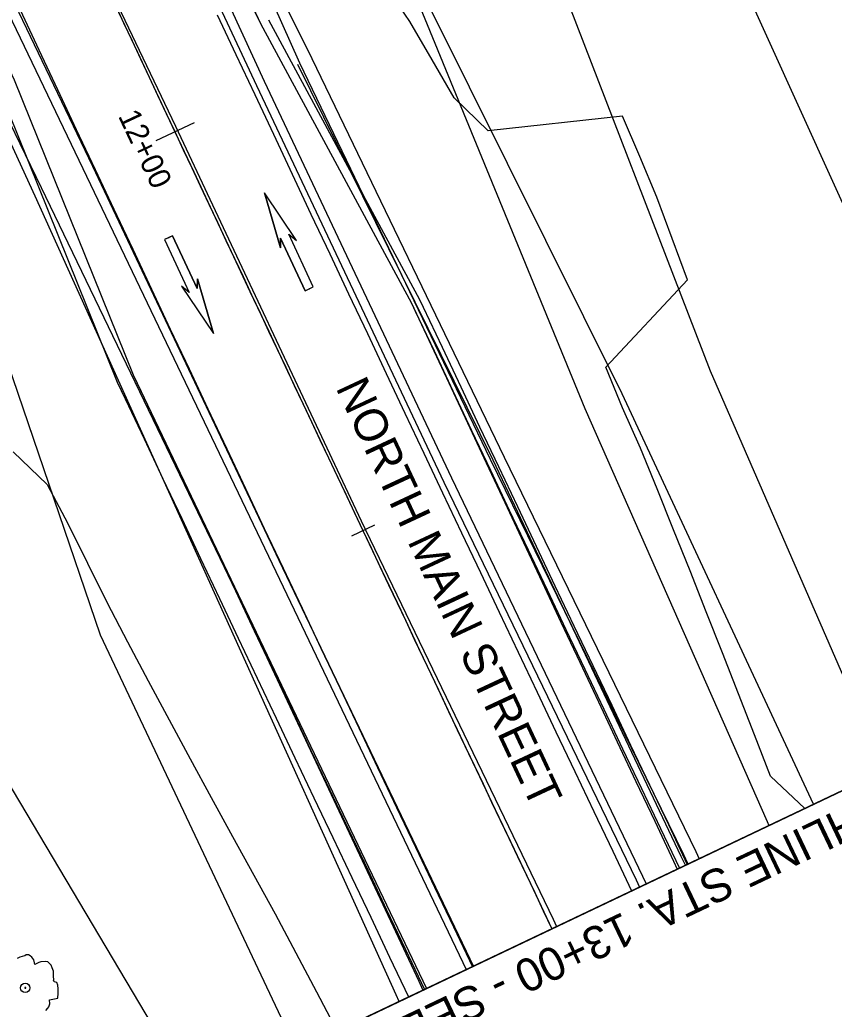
# Model space of a CAD drawing. Extents: x 1040567 to 1041254, y 1126791 to 1127594.
# Drawn here: x 1041010.6 to 1041103, y 1126935.4 to 1127047.7 of the extents above; entities that cross this region are included whole.
import ezdxf

# ---------------------------------------------------------------- set-up
doc = ezdxf.new("R2010")
doc.units = 0
for name, color, linetype in [('AC_P', 7, 'Continuous'), ('ACSR_P_T', 7, 'Continuous'), ('ACSRT_P', 7, 'Continuous'), ('clip boundary', 7, 'Continuous'), ('LABL', 7, 'Continuous'), ('LELB', 7, 'Continuous'), ('LFILL_P', 7, 'Continuous'), ('LTD', 7, 'Continuous'), ('NML_P', 7, 'Continuous'), ('NML_P_T', 7, 'Continuous'), ('O_Details_Text Title and Subtitle Proposed_P_T', 7, 'Continuous'), ('PE', 7, 'Continuous'), ('PE_P', 7, 'Continuous'), ('PET_P', 7, 'Continuous'), ('PSU', 7, 'Continuous'), ('RBS_P', 7, 'Continuous'), ('RGB_P', 7, 'Continuous'), ('RGC', 7, 'Continuous'), ('STFBY', 7, 'Continuous'), ('STFBY_P', 7, 'Continuous'), ('STSEW', 7, 'Continuous'), ('STSEY_P_T', 7, 'Continuous'), ('UEO', 7, 'Continuous')]:
    doc.layers.add(name, color=color, linetype=linetype)

msp = doc.modelspace()

# ---------------------------------------------------------------- linework, layer by layer
at = {"layer": 'AC_P'}
msp.add_arc((1059129.31, 1135540.78), 20000, 205.038741, 205.455638, dxfattribs=at)
at = {"layer": 'ACSRT_P'}
for points in [[(1041030.36, 1127035.96), (1041026.02, 1127033.92)], [(1041050.81, 1126990.33), (1041048.21, 1126989.09)], [(1041073.11, 1126945.57), (1041068.78, 1126943.51)]]:
    msp.add_lwpolyline(points, dxfattribs=at)
at = {"layer": 'clip boundary'}
msp.add_lwpolyline([(1040984.84, 1127512.73), (1041214.88, 1127013.05), (1040933.62, 1126879.17), (1040829.04, 1127018.95), (1040710.75, 1127268.88), (1040738.34, 1127281.77), (1040695.57, 1127374.92)], close=True, dxfattribs=at)
at = {"layer": 'LABL'}
msp.add_lwpolyline([(1041100.61, 1126958.66), (1041100.32, 1126959.26), (1041078.9, 1127005.21), (1041057.26, 1127048.74), (1041046.69, 1127067.39), (1041035.09, 1127091.47)], dxfattribs=at)
at = {"layer": 'LELB'}
for points in [[(1041108.64, 1126962.48), (1041088.94, 1127007.81), (1041071.29, 1127053.6), (1041055, 1127089.77)], [(1041025.59, 1127087.09), (1041045.55, 1127067.24), (1041055.92, 1127049.25), (1041074.68, 1127003.57), (1041095.34, 1126956.71), (1041095.55, 1126956.25)], [(1040987.11, 1127074.81), (1040992.41, 1127065.56), (1040989.3, 1127059.25), (1040989.75, 1127046.81), (1041003.6, 1127024.16), (1041003.93, 1127024.17), (1041019.73, 1126977.88), (1041041.18, 1126932.42), (1041041.98, 1126930.75)], [(1041030.52, 1126925.29), (1041030.18, 1126925.98), (1041006.02, 1126966.59), (1040984.12, 1127013.45), (1040964.74, 1127050.78), (1040957.76, 1127065.57)]]:
    msp.add_lwpolyline(points, dxfattribs=at)
at = {"layer": 'LFILL_P'}
for points in [[(1041099.63, 1126958.19), (1041095.72, 1126961.86), (1041093.92, 1126966.53), (1041092.11, 1126971.2), (1041090.28, 1126975.86), (1041088.44, 1126980.51), (1041086.6, 1126985.16), (1041084.73, 1126989.8), (1041082.86, 1126994.44), (1041080.98, 1126999.07), (1041078.96, 1127003.64), (1041077.05, 1127008.26), (1041086.3, 1127018.15), (1041084.57, 1127022.85), (1041082.84, 1127027.55), (1041080.92, 1127032.16), (1041078.95, 1127036.74), (1041063.72, 1127035.08), (1041059.87, 1127038.79), (1041057.37, 1127043.13), (1041054.82, 1127047.45), (1041052.01, 1127051.65)], [(1041009.84, 1126998.65), (1041013.69, 1126994.93), (1041016.04, 1126990.5), (1041018.26, 1126986.01), (1041020.51, 1126981.53), (1041022.8, 1126977.08), (1041025.16, 1126972.65), (1041027.53, 1126968.24), (1041029.91, 1126963.82), (1041032.31, 1126959.42), (1041034.72, 1126955.02), (1041037.15, 1126950.63), (1041039.54, 1126946.22), (1041041.89, 1126941.8), (1041044.24, 1126937.37), (1041046.58, 1126932.94)]]:
    msp.add_lwpolyline(points, dxfattribs=at)
at = {"layer": 'LTD'}
for points in [[(1041014.8, 1126938.43), (1041014.53, 1126938.53), (1041014.44, 1126938.65), (1041014.47, 1126938.74), (1041014.41, 1126939.17), (1041014.41, 1126939.72), (1041014.29, 1126940.12), (1041014.14, 1126940.42), (1041013.78, 1126940.78), (1041013.51, 1126940.84), (1041012.98, 1126940.78), (1041012.76, 1126940.72), (1041012.37, 1126940.51), (1041012.31, 1126940.48), (1041012.25, 1126940.69), (1041012.19, 1126941.02), (1041011.98, 1126941.33), (1041011.77, 1126941.48), (1041011.59, 1126941.57), (1041011.34, 1126941.57), (1041011.16, 1126941.48), (1041010.86, 1126941.39), (1041010.62, 1126941.33), (1041010.32, 1126941.15)], [(1041011.27, 1126937.83), (1041011.27, 1126937.83), (1041011.27, 1126937.83), (1041011.27, 1126937.85), (1041011.27, 1126937.85), (1041011.27, 1126937.85), (1041011.27, 1126937.86), (1041011.25, 1126937.86), (1041011.25, 1126937.86), (1041011.25, 1126937.86), (1041011.25, 1126937.86), (1041011.25, 1126937.88), (1041011.24, 1126937.88), (1041011.24, 1126937.88), (1041011.24, 1126937.88), (1041011.22, 1126937.88), (1041011.22, 1126937.88), (1041011.22, 1126937.88), (1041011.21, 1126937.88), (1041011.21, 1126937.88), (1041011.21, 1126937.88), (1041011.19, 1126937.88), (1041011.19, 1126937.86), (1041011.19, 1126937.86), (1041011.19, 1126937.86), (1041011.18, 1126937.86), (1041011.18, 1126937.86), (1041011.18, 1126937.85), (1041011.18, 1126937.85), (1041011.18, 1126937.85), (1041011.18, 1126937.83), (1041011.18, 1126937.83), (1041011.18, 1126937.83), (1041011.18, 1126937.82), (1041011.18, 1126937.82), (1041011.18, 1126937.82), (1041011.18, 1126937.8), (1041011.18, 1126937.8), (1041011.19, 1126937.8), (1041011.19, 1126937.8), (1041011.19, 1126937.79), (1041011.19, 1126937.79), (1041011.21, 1126937.79), (1041011.21, 1126937.79), (1041011.21, 1126937.79), (1041011.22, 1126937.79), (1041011.22, 1126937.79), (1041011.22, 1126937.79), (1041011.24, 1126937.79), (1041011.24, 1126937.79), (1041011.24, 1126937.79), (1041011.25, 1126937.79), (1041011.25, 1126937.79), (1041011.25, 1126937.8), (1041011.25, 1126937.8), (1041011.25, 1126937.8), (1041011.27, 1126937.8), (1041011.27, 1126937.82), (1041011.27, 1126937.82), (1041011.27, 1126937.82), (1041011.27, 1126937.83)], [(1041014.92, 1126936.66), (1041014.96, 1126937.23), (1041014.96, 1126937.71), (1041014.9, 1126938.14), (1041014.8, 1126938.43)], [(1041013.55, 1126935.25), (1041013.78, 1126935.52), (1041013.9, 1126935.7), (1041013.99, 1126936.04), (1041013.96, 1126936.47), (1041014.17, 1126936.5), (1041014.92, 1126936.66)]]:
    msp.add_lwpolyline(points, dxfattribs=at)
msp.add_circle((1041011.22, 1126937.83), 0.533, dxfattribs=at)
at = {"layer": 'NML_P'}
msp.add_line((1040940.57, 1126882.48), (1041214.88, 1127013.05), dxfattribs=at)
at = {"layer": 'O_Details_Text Title and Subtitle Proposed_P_T'}
for p, q in [((1041040.15, 1127021.79), (1041038.35, 1127028.01)), ((1041041.96, 1127022.63), (1041038.35, 1127028.01)), ((1041041.09, 1127023.33), (1041041.96, 1127022.63)), ((1041027.48, 1127022.93), (1041027.45, 1127022.92)), ((1041027.48, 1127022.91), (1041027.46, 1127022.9)), ((1041030.75, 1127018.28), (1041032.55, 1127012.06)), ((1041028.94, 1127017.43), (1041032.55, 1127012.06)), ((1041029.82, 1127016.74), (1041028.94, 1127017.43)), ((1041043.42, 1127017.15), (1041043.44, 1127017.17)), ((1041043.43, 1127017.14), (1041043.45, 1127017.15))]:
    msp.add_line(p, q, dxfattribs=at)
at = {"layer": 'PE'}
for points in [[(1041025.42, 1127071.09), (1041025.75, 1127068.01), (1041038.32, 1127040.71), (1041059.56, 1126995.68), (1041081.2, 1126950.5), (1041081.62, 1126949.62)], [(1040998.53, 1127064.86), (1041002.59, 1127062.38), (1041017.74, 1127030.79), (1041039.21, 1126985.95), (1041060.83, 1126940.73), (1041061.22, 1126939.91)]]:
    msp.add_lwpolyline(points, dxfattribs=at)
at = {"layer": 'PE_P'}
for p, q in [((1041037.88, 1127047.24), (1041055.02, 1127015.51)), ((1041009.96, 1127040.83), (1041023.46, 1127007.4))]:
    msp.add_line(p, q, dxfattribs=at)
for points in [[(1040916.89, 1127306.16), (1041021.78, 1127081.61), (1041023.9, 1127077.08), (1041026.01, 1127072.56), (1041028.13, 1127068.03), (1041030.25, 1127063.51), (1041032.37, 1127058.98), (1041034.49, 1127054.46), (1041036.61, 1127049.94), (1041037.88, 1127047.24)], [(1041055.02, 1127015.51), (1041055.44, 1127014.62), (1041057.57, 1127010.1), (1041059.7, 1127005.58), (1041061.84, 1127001.07), (1041063.97, 1126996.55), (1041066.11, 1126992.04), (1041068.25, 1126987.52), (1041070.39, 1126983), (1041072.53, 1126978.49), (1041074.67, 1126973.98), (1041076.81, 1126969.46), (1041078.95, 1126964.95), (1041081.1, 1126960.44), (1041083.24, 1126955.93), (1041085.39, 1126951.41)], [(1041023.46, 1127007.4), (1041024.36, 1127005.49), (1041026.5, 1127000.97), (1041028.63, 1126996.44), (1041030.77, 1126991.92), (1041032.91, 1126987.39), (1041035.05, 1126982.87), (1041037.19, 1126978.35), (1041039.33, 1126973.82), (1041041.47, 1126969.3), (1041043.61, 1126964.78), (1041045.76, 1126960.26), (1041047.9, 1126955.74), (1041050.05, 1126951.22), (1041052.2, 1126946.7), (1041054.35, 1126942.18), (1041056.5, 1126937.66)]]:
    msp.add_lwpolyline(points, dxfattribs=at)
at = {"layer": 'PET_P'}
for points in [[(1041010.64, 1127048.8), (1041012.76, 1127044.27), (1041014.89, 1127039.74), (1041017.01, 1127035.21), (1041019.14, 1127030.68), (1041021.27, 1127026.16), (1041023.4, 1127021.63), (1041025.53, 1127017.1), (1041027.66, 1127012.58), (1041029.79, 1127008.05), (1041031.92, 1127003.53), (1041034.06, 1126999), (1041036.19, 1126994.48), (1041038.33, 1126989.96), (1041040.47, 1126985.43), (1041042.61, 1126980.91), (1041044.75, 1126976.39), (1041046.89, 1126971.87), (1041049.03, 1126967.35), (1041051.18, 1126962.83), (1041053.32, 1126958.31), (1041055.47, 1126953.79), (1041057.62, 1126949.27), (1041059.77, 1126944.76), (1041061.92, 1126940.24)], [(1041032.99, 1127048.24), (1041035.11, 1127043.71), (1041037.24, 1127039.19), (1041039.37, 1127034.67), (1041041.49, 1127030.14), (1041043.62, 1127025.62), (1041045.75, 1127021.1), (1041047.88, 1127016.58), (1041050.01, 1127012.06), (1041052.14, 1127007.54), (1041054.28, 1127003.02), (1041056.41, 1126998.5), (1041058.55, 1126993.99), (1041060.69, 1126989.47), (1041062.83, 1126984.95), (1041064.97, 1126980.44), (1041067.11, 1126975.92), (1041069.25, 1126971.4), (1041071.39, 1126966.89), (1041073.53, 1126962.38), (1041075.68, 1126957.86), (1041077.83, 1126953.35), (1041079.97, 1126948.84)]]:
    msp.add_lwpolyline(points, dxfattribs=at)
at = {"layer": 'PSU'}
for points in [[(1041086.38, 1126951.88), (1041085.9, 1126952.92), (1041063.98, 1126997.78), (1041042.37, 1127042.73), (1041029.48, 1127071.68)], [(1040996.15, 1127063.38), (1041013.01, 1127028.63), (1041034.8, 1126983.45), (1041055.84, 1126938.59), (1041056.32, 1126937.58)], [(1041086.08, 1126951.74), (1041085.6, 1126952.73), (1041064.28, 1126997.69), (1041042.14, 1127042.6)]]:
    msp.add_lwpolyline(points, dxfattribs=at)
at = {"layer": 'RBS_P'}
for p, q in [((1041038.79, 1127047.66), (1041055.93, 1127015.93)), ((1041008.15, 1127039.98), (1041021.65, 1127006.55))]:
    msp.add_line(p, q, dxfattribs=at)
for points in [[(1041055.93, 1127015.93), (1041056.34, 1127015.04), (1041058.48, 1127010.53), (1041060.61, 1127006.01), (1041062.74, 1127001.49), (1041064.88, 1126996.97), (1041067.02, 1126992.46), (1041069.15, 1126987.94), (1041071.29, 1126983.43), (1041073.43, 1126978.91), (1041075.57, 1126974.4), (1041077.72, 1126969.89), (1041079.86, 1126965.37), (1041082, 1126960.86), (1041084.15, 1126956.35), (1041086.29, 1126951.84)], [(1041021.65, 1127006.55), (1041022.55, 1127004.64), (1041024.69, 1127000.12), (1041026.82, 1126995.59), (1041028.96, 1126991.07), (1041031.1, 1126986.54), (1041033.24, 1126982.02), (1041035.38, 1126977.5), (1041037.52, 1126972.97), (1041039.66, 1126968.45), (1041041.8, 1126963.93), (1041043.95, 1126959.41), (1041046.09, 1126954.89), (1041048.24, 1126950.37), (1041050.39, 1126945.85), (1041052.54, 1126941.33), (1041054.69, 1126936.81), (1041054.69, 1126936.8)]]:
    msp.add_lwpolyline(points, dxfattribs=at)
at = {"layer": 'RGB_P'}
for points in [[(1041012.46, 1127101.57), (1041037.88, 1127047.24), (1041055.02, 1127015.51), (1041059.25, 1127006.46), (1041061.37, 1127001.94), (1041063.49, 1126997.41), (1041065.6, 1126992.89), (1041067.72, 1126988.37), (1041069.85, 1126983.85), (1041071.97, 1126979.32), (1041074.09, 1126974.8), (1041076.22, 1126970.28), (1041078.34, 1126965.76), (1041080.47, 1126961.24), (1041082.6, 1126956.73), (1041084.73, 1126952.21), (1041085.15, 1126951.3)], [(1040984.54, 1127095.18), (1041009.96, 1127040.83), (1041023.46, 1127007.4), (1041056.73, 1126937.77)]]:
    msp.add_lwpolyline(points, dxfattribs=at)
at = {"layer": 'RGC'}
for points in [[(1041029.62, 1127071.64), (1041043.7, 1127043.26), (1041065.53, 1126998.03), (1041087.25, 1126953.32), (1041087.65, 1126952.49)], [(1041053.63, 1126936.29), (1041053.28, 1126937.05), (1041032.68, 1126982.66), (1041012.33, 1127027.64), (1040996.02, 1127063.22)]]:
    msp.add_lwpolyline(points, dxfattribs=at)
at = {"layer": 'STFBY'}
msp.add_lwpolyline([(1041013.05, 1127067.43), (1041028.26, 1127035.58), (1041049.32, 1126990.81), (1041071.07, 1126945.62), (1041071.47, 1126944.79)], dxfattribs=at)
at = {"layer": 'STFBY_P'}
msp.add_lwpolyline([(1041021.81, 1127048.51), (1041023.94, 1127043.99), (1041026.06, 1127039.46), (1041028.19, 1127034.94), (1041030.32, 1127030.41), (1041032.44, 1127025.89), (1041034.57, 1127021.36), (1041036.7, 1127016.84), (1041038.84, 1127012.32), (1041040.97, 1127007.79), (1041043.1, 1127003.27), (1041045.24, 1126998.75), (1041047.37, 1126994.23), (1041049.51, 1126989.71), (1041051.65, 1126985.19), (1041053.79, 1126980.67), (1041055.93, 1126976.15), (1041058.07, 1126971.63), (1041060.21, 1126967.12), (1041062.36, 1126962.6), (1041064.5, 1126958.08), (1041066.65, 1126953.57), (1041068.8, 1126949.05), (1041070.94, 1126944.54)], dxfattribs=at)
at = {"layer": 'STSEW'}
for points in [[(1041023.26, 1127070.52), (1041037.46, 1127040.2), (1041058.67, 1126995.22), (1041080.48, 1126950.09), (1041080.88, 1126949.27)], [(1041002.07, 1127066.02), (1041018.84, 1127031.05), (1041039.99, 1126986.34), (1041061.65, 1126941.13), (1041062.04, 1126940.3)]]:
    msp.add_lwpolyline(points, dxfattribs=at)
at = {"layer": 'STSEY_P_T'}
for p, q in [((1041041.96, 1127022.63), (1041038.35, 1127028.01)), ((1041038.35, 1127028.01), (1041040.15, 1127021.79)), ((1041043.88, 1127017.35), (1041041.09, 1127023.33)), ((1041043.88, 1127017.35), (1041041.09, 1127023.33)), ((1041041.09, 1127023.33), (1041041.96, 1127022.63)), ((1041027.93, 1127023.14), (1041027.02, 1127022.72)), ((1041027.02, 1127022.72), (1041029.82, 1127016.74)), ((1041027.02, 1127022.72), (1041029.82, 1127016.74)), ((1041027.93, 1127023.14), (1041030.72, 1127017.16)), ((1041030.72, 1127017.16), (1041027.93, 1127023.14)), ((1041040.18, 1127022.9), (1041040.15, 1127021.79)), ((1041040.15, 1127021.79), (1041040.18, 1127022.9)), ((1041042.97, 1127016.92), (1041040.18, 1127022.9)), ((1041040.18, 1127022.9), (1041042.97, 1127016.92)), ((1041030.72, 1127017.16), (1041030.75, 1127018.28)), ((1041030.75, 1127018.28), (1041030.72, 1127017.16)), ((1041032.55, 1127012.06), (1041030.75, 1127018.28)), ((1041029.82, 1127016.74), (1041028.94, 1127017.43)), ((1041028.94, 1127017.43), (1041032.55, 1127012.06)), ((1041042.97, 1127016.92), (1041043.88, 1127017.35))]:
    msp.add_line(p, q, dxfattribs=at)
for points in [[(1041027.93, 1127023.14), (1041027.48, 1127022.93), (1041027.02, 1127022.72)], [(1041042.97, 1127016.92), (1041043.43, 1127017.14), (1041043.88, 1127017.35)]]:
    msp.add_lwpolyline(points, dxfattribs=at)
at = {"layer": 'UEO'}
msp.add_lwpolyline([(1041080.49, 1127078.42), (1041128.78, 1126972.07)], dxfattribs=at)

# ---------------------------------------------------------------- texts
at = {"layer": 'ACSR_P_T'}
msp.add_text('12+00', height=2.496, rotation=295.1692, dxfattribs=at).set_placement((1041021.71, 1127036.76))
at = {"layer": 'NML_P_T'}
msp.add_text('MATCHLINE STA. 13+00 - SEE DWG. GNP-04', height=3.744, rotation=205.4556, dxfattribs=at).set_placement((1041117.71, 1126964.92))
at = {"layer": 'O_Details_Text Title and Subtitle Proposed_P_T'}
msp.add_text('NORTH MAIN STREET', height=3.7536, rotation=295.0387, dxfattribs=at).set_placement((1041046.38, 1127005.94))

doc.saveas('drawing.dxf')
